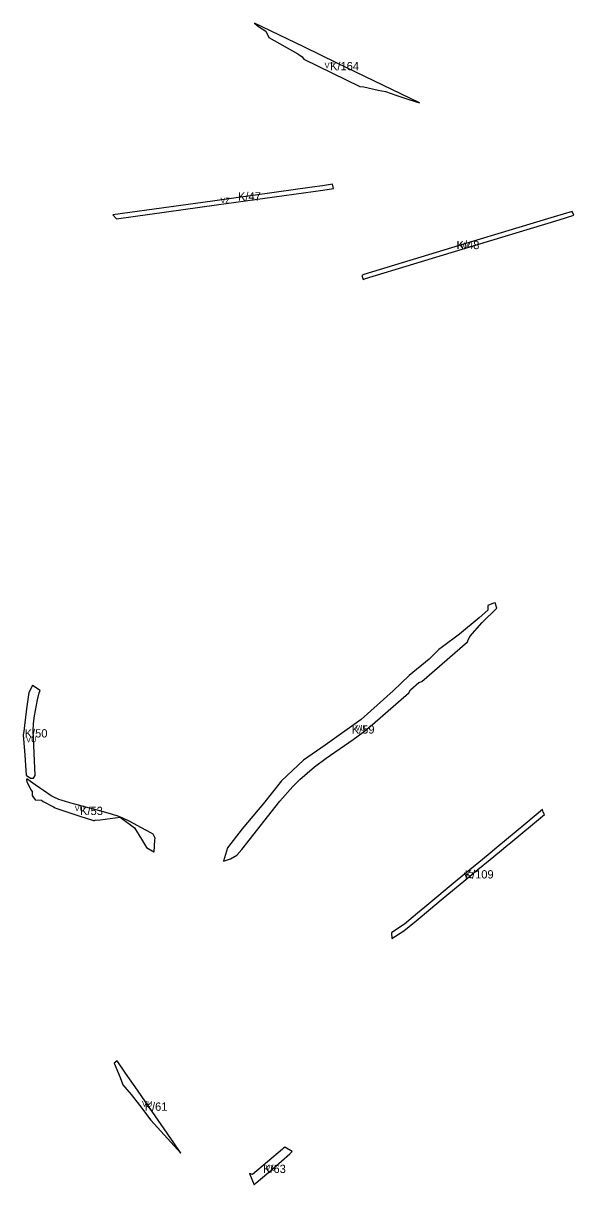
# Model space of a CAD drawing. Extents: x -521939 to -518034, y -1194984 to -1189555.
# Drawn here: x -519031 to -518034, y -1194984 to -1192880 of the extents above; entities that cross this region are included whole.
import ezdxf

# ---------------------------------------------------------------- set-up
doc = ezdxf.new("R2010")
doc.units = 0
for name, color, linetype in [('96111023', 7, 'Continuous'), ('96122023', 7, 'Continuous'), ('96141023', 7, 'Continuous'), ('96202223', 7, 'Continuous')]:
    doc.layers.add(name, color=color, linetype=linetype)

msp = doc.modelspace()

# ---------------------------------------------------------------- linework, layer by layer
at = {"layer": '96111023'}
for points in [[(-518313.58, -1193023.8), (-518462.75, -1192951.72), (-518523.11, -1192922.54), (-518611.93, -1192879.62), (-518611.95, -1192879.61)], [(-518611.95, -1192879.61), (-518604.74, -1192885.62), (-518591.47, -1192894.23)], [(-518591.47, -1192894.23), (-518586.01, -1192905.56)], [(-518586.01, -1192905.56), (-518533.4, -1192935.15), (-518525.77, -1192940.63), (-518522.92, -1192944.85)], [(-518522.92, -1192944.85), (-518472.09, -1192969.41)], [(-518472.09, -1192969.41), (-518421.27, -1192993.97)], [(-518421.27, -1192993.97), (-518421.26, -1192993.97), (-518414.09, -1192994.92), (-518388.43, -1193000.81)], [(-518388.43, -1193000.81), (-518375.31, -1193003.18)], [(-518375.31, -1193003.18), (-518354.48, -1193010.65), (-518345.74, -1193013.45)], [(-518345.74, -1193013.45), (-518332.79, -1193017.61), (-518313.58, -1193023.8)], [(-518471.02, -1193171.35), (-518489.33, -1193173.91)], [(-518469.31, -1193179.19), (-518471.02, -1193171.35)], [(-518489.33, -1193173.91), (-518507.69, -1193176.48), (-518688.29, -1193201.76), (-518868.39, -1193226.97), (-518861.71, -1193234.11), (-518680.88, -1193208.8), (-518488.19, -1193181.83)], [(-518488.19, -1193181.83), (-518469.31, -1193179.19)], [(-518037.03, -1193220.36), (-518069.91, -1193230.34), (-518241.69, -1193282.48), (-518414.03, -1193334.79)], [(-518411.17, -1193342.06), (-518236.07, -1193288.88), (-518060.97, -1193235.7), (-518034.3, -1193227.6)], [(-518034.3, -1193227.6), (-518037.03, -1193220.36)], [(-518414.03, -1193334.79), (-518417.99, -1193336.8)], [(-518417.99, -1193336.8), (-518415.16, -1193344.07)], [(-518415.16, -1193344.07), (-518411.17, -1193342.06)], [(-518176.81, -1193929.72), (-518179.54, -1193930.3), (-518189.98, -1193934.67)], [(-518173.64, -1193939.33), (-518176.81, -1193929.72)], [(-518225.95, -1193998.27), (-518222.25, -1193990.41), (-518200, -1193965.24), (-518173.64, -1193939.33)], [(-518190.04, -1193942.98), (-518205.7, -1193956.46)], [(-518189.98, -1193934.67), (-518190.04, -1193942.98)], [(-518205.7, -1193956.46), (-518240.91, -1193986.11)], [(-518240.91, -1193986.11), (-518271.56, -1194009.45), (-518278.37, -1194013.9)], [(-518655.68, -1194393.54), (-518644.23, -1194386.38), (-518634.76, -1194376.7), (-518566.27, -1194288.86), (-518542.85, -1194262.27), (-518530.28, -1194249.78), (-518503.56, -1194226.5), (-518482.17, -1194210.72), (-518433.41, -1194176.9), (-518415.71, -1194163.89), (-518398.75, -1194149.91), (-518332.7, -1194092.34), (-518329.88, -1194087.32), (-518314.52, -1194073.94), (-518309.55, -1194072.16), (-518226.78, -1194000.03)], [(-518278.37, -1194013.9), (-518296.03, -1194031.57), (-518332.33, -1194061.21)], [(-518226.78, -1194000.03), (-518225.95, -1193998.27)], [(-518332.33, -1194061.21), (-518361.02, -1194088.99), (-518419.1, -1194140.67), (-518483.93, -1194187.46), (-518523.23, -1194214.71)], [(-519020.73, -1194091.88), (-519024.61, -1194121.8), (-519028.49, -1194151.72), (-519029.89, -1194162.52), (-519030.29, -1194165.62), (-519030.69, -1194168.71), (-519027.95, -1194205.37), (-519025.2, -1194242.02)], [(-519013.71, -1194079.07), (-519020.73, -1194091.88)], [(-518999.95, -1194088.17), (-519013.71, -1194079.07)], [(-519004.84, -1194105.44), (-519001.62, -1194092.79), (-518999.95, -1194088.17)], [(-519012.79, -1194161.44), (-519012.2, -1194148.13), (-519010.43, -1194134.4), (-519004.84, -1194105.44)], [(-519012.22, -1194247.18), (-519009.11, -1194242.54), (-519012.79, -1194161.44)], [(-518523.23, -1194214.71), (-518563.39, -1194252.1)], [(-519025.2, -1194242.02), (-519017.78, -1194247.27)], [(-518794.51, -1194380.48), (-518793.68, -1194380.64), (-518792.24, -1194359.26), (-518791.99, -1194355.76), (-518795.83, -1194348.62), (-518799.64, -1194346.49), (-518816.36, -1194337.16), (-518838.06, -1194325.4), (-518851.56, -1194319.21), (-518862.69, -1194315.05), (-518865.77, -1194314.1), (-518872.91, -1194311.92), (-518892.05, -1194306.64), (-518905.25, -1194303.03), (-518910.54, -1194301.58), (-518937.1, -1194294.31), (-518946.44, -1194291.75), (-518954.36, -1194289.64), (-518962.17, -1194287.03), (-518966.08, -1194285.71), (-518975.52, -1194281.45), (-518980.26, -1194279.31), (-518993.95, -1194269.72), (-519001.41, -1194264.41), (-519008.87, -1194259.09), (-519017.53, -1194252.96), (-519023.94, -1194248.41), (-519024.71, -1194250.04), (-519024.49, -1194253.08)], [(-519024.49, -1194253.08), (-519017.06, -1194268.42)], [(-519017.78, -1194247.27), (-519012.22, -1194247.18)], [(-518563.39, -1194252.1), (-518595.65, -1194293.01), (-518634.33, -1194338.71), (-518661.16, -1194373.51)], [(-519017.06, -1194268.42), (-519014.59, -1194271.5), (-519014.52, -1194278.4)], [(-519014.52, -1194278.4), (-519009.2, -1194286.28)], [(-519009.2, -1194286.28), (-518997.55, -1194287.28)], [(-518997.55, -1194287.28), (-518994.7, -1194289.4), (-518975.86, -1194299.17), (-518972.84, -1194300.73), (-518969.65, -1194302.39)], [(-518969.65, -1194302.39), (-518959.1, -1194305.82), (-518939.19, -1194312.3)], [(-518090.78, -1194303.93), (-518120.84, -1194329.01)], [(-518087.28, -1194312.72), (-518089.43, -1194308.57), (-518090.78, -1194303.93)], [(-518939.19, -1194312.3), (-518928.2, -1194315.87)], [(-518928.2, -1194315.87), (-518903.28, -1194323.98)], [(-518903.28, -1194323.98), (-518901.43, -1194323.75)], [(-518901.43, -1194323.75), (-518900.67, -1194323.31)], [(-518900.67, -1194323.31), (-518891.75, -1194322.51)], [(-518891.75, -1194322.51), (-518855.36, -1194317.86)], [(-518855.36, -1194317.86), (-518829.53, -1194336.97), (-518816.88, -1194357.57)], [(-518120.84, -1194329.01), (-518156.04, -1194358.17)], [(-518152.05, -1194366.76), (-518087.28, -1194312.72)], [(-518816.88, -1194357.57), (-518807.62, -1194372.64)], [(-518807.62, -1194372.64), (-518794.51, -1194380.48)], [(-518173.76, -1194372.91), (-518185.81, -1194382.9)], [(-518156.04, -1194358.17), (-518173.76, -1194372.91)], [(-518168.73, -1194380.59), (-518153.38, -1194367.87), (-518152.05, -1194366.76)], [(-518661.16, -1194373.51), (-518668.49, -1194397.81)], [(-518668.49, -1194397.81), (-518655.68, -1194393.54)], [(-518185.81, -1194382.9), (-518199.57, -1194394.33)], [(-518185.85, -1194394.67), (-518168.73, -1194380.59)], [(-518274.04, -1194467.87), (-518229.68, -1194431.04), (-518207.82, -1194412.86), (-518185.85, -1194394.67)], [(-518199.57, -1194394.33), (-518245.06, -1194432.12)], [(-518245.06, -1194432.12), (-518304.03, -1194481.14)], [(-518293.63, -1194484.18), (-518274.04, -1194467.87)], [(-518317.05, -1194491.98), (-518340.81, -1194511.5)], [(-518319.41, -1194505.51), (-518293.63, -1194484.18)], [(-518304.03, -1194481.14), (-518317.05, -1194491.98)], [(-518340.81, -1194511.5), (-518345.29, -1194514.98), (-518364.14, -1194527.29)], [(-518363.86, -1194537.39), (-518341.98, -1194523.73), (-518319.41, -1194505.51)], [(-518364.14, -1194527.29), (-518363.86, -1194537.39)], [(-518860.9, -1194759.36), (-518865.86, -1194763.22)], [(-518865.86, -1194763.22), (-518855.5, -1194789.32)], [(-518845.5, -1194781.65), (-518860.9, -1194759.36)], [(-518855.5, -1194789.32), (-518850.84, -1194801.06)], [(-518838.55, -1194791.71), (-518845.5, -1194781.65)], [(-518831.36, -1194802.11), (-518838.55, -1194791.71)], [(-518850.84, -1194801.06), (-518850.19, -1194802.69)], [(-518850.19, -1194802.69), (-518843.34, -1194811.13)], [(-518843.34, -1194811.13), (-518835.53, -1194820.44)], [(-518824.2, -1194812.48), (-518831.36, -1194802.11)], [(-518745.52, -1194926.78), (-518758.18, -1194908.03), (-518809.54, -1194833.7), (-518824.2, -1194812.48)], [(-518835.53, -1194820.44), (-518820.29, -1194839.32)], [(-518820.29, -1194839.32), (-518800.02, -1194866.93), (-518745.52, -1194926.78)], [(-518561.44, -1194919.5), (-518588.48, -1194942.32), (-518615.53, -1194965.15)], [(-518557.27, -1194915.81), (-518559.35, -1194917.65), (-518561.44, -1194919.5)], [(-518543.87, -1194923.75), (-518557.27, -1194915.81)], [(-518578.49, -1194954.01), (-518547.93, -1194927.89)], [(-518547.93, -1194927.89), (-518543.87, -1194923.75)], [(-518609.05, -1194980.13), (-518578.49, -1194954.01)], [(-518615.53, -1194965.15), (-518621.14, -1194963.55)], [(-518621.14, -1194963.55), (-518612.46, -1194983.75)], [(-518612.46, -1194983.75), (-518609.05, -1194980.13)]]:
    msp.add_lwpolyline(points, dxfattribs=at)
at = {"layer": '96122023'}
for points in [[(-518313.58, -1193023.8), (-518462.75, -1192951.72), (-518523.11, -1192922.54), (-518611.93, -1192879.62), (-518611.95, -1192879.61)], [(-518611.95, -1192879.61), (-518604.74, -1192885.62), (-518591.47, -1192894.23)], [(-518591.47, -1192894.23), (-518586.01, -1192905.56)], [(-518586.01, -1192905.56), (-518533.4, -1192935.15), (-518525.77, -1192940.63), (-518522.92, -1192944.85)], [(-518522.92, -1192944.85), (-518472.09, -1192969.41)], [(-518472.09, -1192969.41), (-518421.27, -1192993.97)], [(-518421.27, -1192993.97), (-518421.26, -1192993.97), (-518414.09, -1192994.92), (-518388.43, -1193000.81)], [(-518388.43, -1193000.81), (-518375.31, -1193003.18)], [(-518375.31, -1193003.18), (-518354.48, -1193010.65), (-518345.74, -1193013.45)], [(-518345.74, -1193013.45), (-518332.79, -1193017.61), (-518313.58, -1193023.8)]]:
    msp.add_lwpolyline(points, dxfattribs=at)
at = {"layer": '96141023'}
for points in [[(-518176.81, -1193929.72), (-518179.54, -1193930.3), (-518189.98, -1193934.67)], [(-518173.64, -1193939.33), (-518176.81, -1193929.72)], [(-518225.95, -1193998.27), (-518222.25, -1193990.41), (-518200, -1193965.24), (-518173.64, -1193939.33)], [(-518190.04, -1193942.98), (-518205.7, -1193956.46)], [(-518189.98, -1193934.67), (-518190.04, -1193942.98)], [(-518205.7, -1193956.46), (-518240.91, -1193986.11)], [(-518240.91, -1193986.11), (-518271.56, -1194009.45), (-518278.37, -1194013.9)], [(-518655.68, -1194393.54), (-518644.23, -1194386.38), (-518634.76, -1194376.7), (-518566.27, -1194288.86), (-518542.85, -1194262.27), (-518530.28, -1194249.78), (-518503.56, -1194226.5), (-518482.17, -1194210.72), (-518433.41, -1194176.9), (-518415.71, -1194163.89), (-518398.75, -1194149.91), (-518332.7, -1194092.34), (-518329.88, -1194087.32), (-518314.52, -1194073.94), (-518309.55, -1194072.16), (-518226.78, -1194000.03)], [(-518278.37, -1194013.9), (-518296.03, -1194031.57), (-518332.33, -1194061.21)], [(-518226.78, -1194000.03), (-518225.95, -1193998.27)], [(-518332.33, -1194061.21), (-518361.02, -1194088.99), (-518419.1, -1194140.67), (-518483.93, -1194187.46), (-518523.23, -1194214.71)], [(-519020.73, -1194091.88), (-519024.61, -1194121.8), (-519028.49, -1194151.72), (-519029.89, -1194162.52), (-519030.29, -1194165.62), (-519030.69, -1194168.71), (-519027.95, -1194205.37), (-519025.2, -1194242.02)], [(-519013.71, -1194079.07), (-519020.73, -1194091.88)], [(-518999.95, -1194088.17), (-519013.71, -1194079.07)], [(-519004.84, -1194105.44), (-519001.62, -1194092.79), (-518999.95, -1194088.17)], [(-519012.79, -1194161.44), (-519012.2, -1194148.13), (-519010.43, -1194134.4), (-519004.84, -1194105.44)], [(-519012.22, -1194247.18), (-519009.11, -1194242.54), (-519012.79, -1194161.44)], [(-518523.23, -1194214.71), (-518563.39, -1194252.1)], [(-519025.2, -1194242.02), (-519017.78, -1194247.27)], [(-519023.94, -1194248.41), (-519024.71, -1194250.04), (-519024.49, -1194253.08)], [(-519024.49, -1194253.08), (-519017.06, -1194268.42)], [(-519017.53, -1194252.96), (-519023.94, -1194248.41)], [(-519017.78, -1194247.27), (-519012.22, -1194247.18)], [(-519008.87, -1194259.09), (-519017.53, -1194252.96)], [(-519001.41, -1194264.41), (-519008.87, -1194259.09)], [(-518975.52, -1194281.45), (-518980.26, -1194279.31), (-518993.95, -1194269.72), (-519001.41, -1194264.41)], [(-518563.39, -1194252.1), (-518595.65, -1194293.01), (-518634.33, -1194338.71), (-518661.16, -1194373.51)], [(-519017.06, -1194268.42), (-519014.59, -1194271.5)], [(-519014.59, -1194271.5), (-519014.52, -1194278.4), (-519009.2, -1194286.28)], [(-519009.2, -1194286.28), (-518997.55, -1194287.28), (-518994.7, -1194289.4)], [(-518966.08, -1194285.71), (-518975.52, -1194281.45)], [(-518937.1, -1194294.31), (-518946.44, -1194291.75), (-518954.36, -1194289.64), (-518962.17, -1194287.03), (-518966.08, -1194285.71)], [(-518994.7, -1194289.4), (-518975.86, -1194299.17), (-518972.84, -1194300.73)], [(-518972.84, -1194300.73), (-518969.65, -1194302.39)], [(-518969.65, -1194302.39), (-518959.1, -1194305.82)], [(-518959.1, -1194305.82), (-518939.19, -1194312.3)], [(-518905.25, -1194303.03), (-518910.54, -1194301.58), (-518937.1, -1194294.31)], [(-518892.05, -1194306.64), (-518905.25, -1194303.03)], [(-518872.91, -1194311.92), (-518892.05, -1194306.64)], [(-518939.19, -1194312.3), (-518928.2, -1194315.87)], [(-518928.2, -1194315.87), (-518903.28, -1194323.98)], [(-518903.28, -1194323.98), (-518901.43, -1194323.75)], [(-518901.43, -1194323.75), (-518900.67, -1194323.31)], [(-518900.67, -1194323.31), (-518891.75, -1194322.51)], [(-518891.75, -1194322.51), (-518855.36, -1194317.86), (-518829.53, -1194336.97)], [(-518865.77, -1194314.1), (-518872.91, -1194311.92)], [(-518851.56, -1194319.21), (-518862.69, -1194315.05), (-518865.77, -1194314.1)], [(-518816.36, -1194337.16), (-518838.06, -1194325.4), (-518851.56, -1194319.21)], [(-518829.53, -1194336.97), (-518816.88, -1194357.57), (-518807.62, -1194372.64)], [(-518795.83, -1194348.62), (-518799.64, -1194346.49), (-518816.36, -1194337.16)], [(-518793.68, -1194380.64), (-518792.24, -1194359.26), (-518791.99, -1194355.76), (-518795.83, -1194348.62)], [(-518807.62, -1194372.64), (-518794.51, -1194380.48)], [(-518794.51, -1194380.48), (-518793.68, -1194380.64)], [(-518661.16, -1194373.51), (-518668.49, -1194397.81)], [(-518668.49, -1194397.81), (-518655.68, -1194393.54)], [(-518860.9, -1194759.36), (-518865.86, -1194763.22)], [(-518865.86, -1194763.22), (-518855.5, -1194789.32)], [(-518845.5, -1194781.65), (-518860.9, -1194759.36)], [(-518855.5, -1194789.32), (-518850.84, -1194801.06)], [(-518838.55, -1194791.71), (-518845.5, -1194781.65)], [(-518831.36, -1194802.11), (-518838.55, -1194791.71)], [(-518850.84, -1194801.06), (-518850.19, -1194802.69)], [(-518850.19, -1194802.69), (-518843.34, -1194811.13)], [(-518843.34, -1194811.13), (-518835.53, -1194820.44)], [(-518824.2, -1194812.48), (-518831.36, -1194802.11)], [(-518745.52, -1194926.78), (-518758.18, -1194908.03), (-518809.54, -1194833.7), (-518824.2, -1194812.48)], [(-518835.53, -1194820.44), (-518820.29, -1194839.32)], [(-518820.29, -1194839.32), (-518800.02, -1194866.93), (-518745.52, -1194926.78)], [(-518561.44, -1194919.5), (-518588.48, -1194942.32), (-518615.53, -1194965.15)], [(-518557.27, -1194915.81), (-518559.35, -1194917.65), (-518561.44, -1194919.5)], [(-518543.87, -1194923.75), (-518557.27, -1194915.81)], [(-518578.49, -1194954.01), (-518547.93, -1194927.89)], [(-518547.93, -1194927.89), (-518543.87, -1194923.75)], [(-518609.05, -1194980.13), (-518578.49, -1194954.01)], [(-518615.53, -1194965.15), (-518621.14, -1194963.55)], [(-518621.14, -1194963.55), (-518612.46, -1194983.75)], [(-518612.46, -1194983.75), (-518609.05, -1194980.13)]]:
    msp.add_lwpolyline(points, dxfattribs=at)
at = {"layer": '96202223'}
for points in [[(-518471.02, -1193171.35), (-518489.33, -1193173.91)], [(-518469.31, -1193179.19), (-518471.02, -1193171.35)], [(-518489.33, -1193173.91), (-518507.69, -1193176.48), (-518688.29, -1193201.76), (-518868.39, -1193226.97), (-518861.71, -1193234.11), (-518680.88, -1193208.8), (-518488.19, -1193181.83)], [(-518488.19, -1193181.83), (-518469.31, -1193179.19)], [(-518037.03, -1193220.36), (-518069.91, -1193230.34), (-518241.69, -1193282.48), (-518414.03, -1193334.79)], [(-518411.17, -1193342.06), (-518236.07, -1193288.88), (-518060.97, -1193235.7), (-518034.3, -1193227.6)], [(-518034.3, -1193227.6), (-518037.03, -1193220.36)], [(-518414.03, -1193334.79), (-518417.99, -1193336.8)], [(-518417.99, -1193336.8), (-518415.16, -1193344.07)], [(-518415.16, -1193344.07), (-518411.17, -1193342.06)], [(-518090.78, -1194303.93), (-518120.84, -1194329.01)], [(-518087.28, -1194312.72), (-518089.43, -1194308.57), (-518090.78, -1194303.93)], [(-518120.84, -1194329.01), (-518156.04, -1194358.17)], [(-518152.05, -1194366.76), (-518087.28, -1194312.72)], [(-518173.76, -1194372.91), (-518185.81, -1194382.9)], [(-518156.04, -1194358.17), (-518173.76, -1194372.91)], [(-518168.73, -1194380.59), (-518153.38, -1194367.87), (-518152.05, -1194366.76)], [(-518185.81, -1194382.9), (-518199.57, -1194394.33)], [(-518185.85, -1194394.67), (-518168.73, -1194380.59)], [(-518274.04, -1194467.87), (-518229.68, -1194431.04), (-518207.82, -1194412.86), (-518185.85, -1194394.67)], [(-518199.57, -1194394.33), (-518245.06, -1194432.12)], [(-518245.06, -1194432.12), (-518304.03, -1194481.14)], [(-518293.63, -1194484.18), (-518274.04, -1194467.87)], [(-518317.05, -1194491.98), (-518340.81, -1194511.5)], [(-518319.41, -1194505.51), (-518293.63, -1194484.18)], [(-518304.03, -1194481.14), (-518317.05, -1194491.98)], [(-518340.81, -1194511.5), (-518345.29, -1194514.98), (-518364.14, -1194527.29)], [(-518363.86, -1194537.39), (-518341.98, -1194523.73), (-518319.41, -1194505.51)], [(-518364.14, -1194527.29), (-518363.86, -1194537.39)]]:
    msp.add_lwpolyline(points, dxfattribs=at)

# ---------------------------------------------------------------- texts
at = {"layer": '96111023'}
for s, rotation, p in [('K/164', 360, (-518475.42, -1192964.82)), ('K/47', 360, (-518642, -1193200.81)), ('K/48', 360, (-518246.39, -1193288.82)), ('K/50', 0, (-519028.14, -1194173.45)), ('K/53', 0, (-518927.82, -1194313.98)), ('K/109', 360, (-518231.76, -1194428.88)), ('K/61', 360, (-518810.98, -1194849.7)), ('K/63', 360, (-518596.69, -1194962.38))]:
    msp.add_text(s, height=15, rotation=rotation, dxfattribs=at).set_placement(p)
msp.add_text('K/59', height=15, dxfattribs=at).set_placement((-518436.26, -1194166.38))
at = {"layer": '96122023'}
msp.add_text('VT', height=10, rotation=0, dxfattribs=at).set_placement((-518485.27, -1192961.17))
at = {"layer": '96141023'}
for rotation, p in [(0, (-518429.62, -1194161.18)), (360, (-519025.61, -1194182.17)), (360, (-518937.52, -1194306.8)), (0, (-518815.72, -1194842.02)), (0, (-518592.02, -1194957.99))]:
    msp.add_text('VU', height=10, rotation=rotation, dxfattribs=at).set_placement(p)
at = {"layer": '96202223'}
for rotation, p in [(0, (-518673.75, -1193205.54)), (0, (-518239.87, -1193286.67)), (360, (-518233.24, -1194428.03))]:
    msp.add_text('VZ', height=10, rotation=rotation, dxfattribs=at).set_placement(p)

doc.saveas('drawing.dxf')
